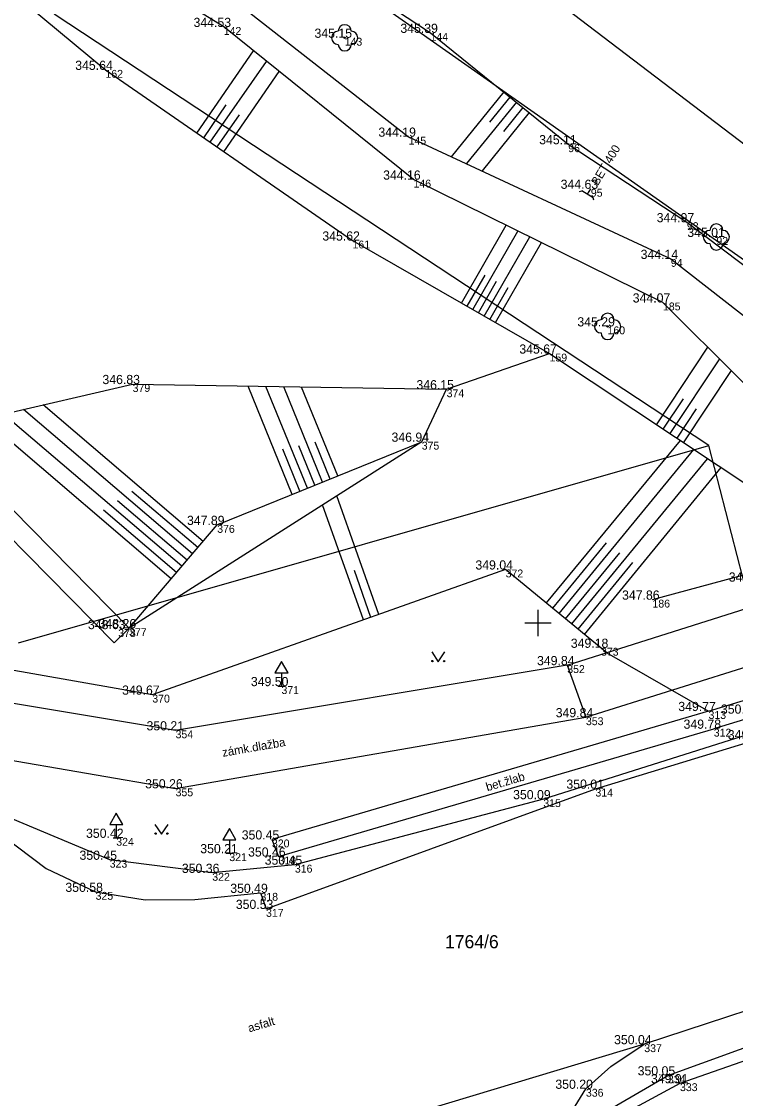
# Model space of a CAD drawing. Extents: x -614046 to -613877, y -1156755 to -1156623.
# Drawn here: x -613975.76 to -613953.98, y -1156734.51 to -1156701.64 of the extents above; entities that cross this region are included whole.
import ezdxf

# ---------------------------------------------------------------- set-up
doc = ezdxf.new("R2010")
doc.units = 0
for name, color, linetype in [('1-bod', 7, 'Continuous'), ('10-silnice', 7, 'Continuous'), ('11-zpevněné plochy', 7, 'Continuous'), ('14-terénní hrany', 7, 'Continuous'), ('15-šrafy', 7, 'Continuous'), ('16-vodní tok', 7, 'Continuous'), ('2-bod výška', 7, 'Continuous'), ('22-stromy', 7, 'Continuous'), ('27-kanalizace značky', 7, 'Continuous'), ('3-bod číslo', 7, 'Continuous'), ('34-dopravní značky', 7, 'Continuous'), ('36-Značky kultur', 7, 'Continuous'), ('40-popisy povrchů', 7, 'Continuous'), ('50-hranice parcel KN', 7, 'Continuous'), ('61-hektarová síť', 7, 'Continuous'), ('7-plot', 7, 'Continuous'), ('9-zábradlí svodidlo', 7, 'Continuous')]:
    doc.layers.add(name, color=color, linetype=linetype)

# ---------------------------------------------------------------- blocks, each defined once
blk = doc.blocks.new('3.13_1')
at = {"layer": '22-stromy'}
blk.add_circle((0, 0), 0.05, dxfattribs=at)
for centre, start, end in [((0, 0.5), 0, 180), ((-0.5, 0), 90, 270), ((0.5, 0), 270, 90), ((0, -0.5), 180, 0)]:
    blk.add_arc(centre, 0.5, start, end, dxfattribs=at)
blk = doc.blocks.new('5.270')
at = {"layer": '34-dopravní značky'}
for p, q in [((0.001, 1.02), (0.001, 0.001)), ((-0.249, 0.002), (0.251, 0.002))]:
    blk.add_line(p, q, dxfattribs=at)
blk.add_lwpolyline([(-0.499, 1.019), (0.501, 1.02), (0.001, 1.884)], close=True, dxfattribs=at)
blk = doc.blocks.new('VT')
at = {"layer": '27-kanalizace značky'}
for p, q in [((-0.629, 0.641), (-0.488, 0.5)), ((-0.488, -0.5), (-0.488, 0.5)), ((-0.488, 0), (0, 0)), ((-0.629, -0.641), (-0.488, -0.5))]:
    blk.add_line(p, q, dxfattribs=at)
blk = doc.blocks.new('3.14')
at = {"layer": '36-Značky kultur'}
blk.add_lwpolyline([(-0.5, 0.75), (0, 0), (0.5, 0.75)], dxfattribs=at)
for centre in [(-0.45, 0.05), (0.449, 0.05)]:
    blk.add_circle(centre, 0.05, dxfattribs=at)
blk = doc.blocks.new('POINT_DISPLAY')
blk.add_line((0, 0), (0, 0))

msp = doc.modelspace()

# ---------------------------------------------------------------- linework, layer by layer
at = {"layer": '10-silnice'}
for points in [[(-614040.86, -1156670.12), (-614026.04, -1156676.19), (-614020.49, -1156678.89), (-614017.81, -1156680.62), (-614014.97, -1156682.84), (-614010.02, -1156687.67), (-614005.03, -1156692.4), (-614001.46, -1156696.62), (-613996.56, -1156702.86), (-613991.22, -1156709.86), (-613982.03, -1156721.02), (-613980.56, -1156722.02), (-613978.09, -1156724.42), (-613976.34, -1156726.49), (-613975.01, -1156727.5), (-613973.5, -1156728.21), (-613971.99, -1156728.45), (-613970.47, -1156728.44), (-613968.47, -1156728.24), (-613968.3, -1156728.73), (-613958.25, -1156725.06), (-613953.29, -1156723.55)], [(-613903.37, -1156719.95), (-613913.49, -1156721.34), (-613924.71, -1156723.64), (-613933.07, -1156725.62), (-613940.71, -1156727.79), (-613951.06, -1156730.99), (-613956.76, -1156732.86), (-613974.57, -1156738.23), (-613984.2, -1156741.44), (-613994.97, -1156744.83), (-613999.58, -1156745.99)], [(-613959.8, -1156738.57), (-613959.59, -1156736.54), (-613959.25, -1156735.36), (-613958.54, -1156734.22), (-613957.78, -1156733.54), (-613956.76, -1156732.86)]]:
    msp.add_lwpolyline(points, dxfattribs=at)
at = {"layer": '11-zpevněné plochy'}
for p, q in [((-613959.11, -1156721.29), (-613935.9, -1156713.93)), ((-613956.51, -1156719.29), (-613939.14, -1156714.57)), ((-613958.54, -1156722.88), (-613935.4, -1156715.58)), ((-613954.8, -1156722.69), (-613948.43, -1156720.74)), ((-613959.11, -1156721.29), (-613971.06, -1156723.28)), ((-613959.11, -1156721.29), (-613958.54, -1156722.88)), ((-613948.23, -1156721.29), (-613954.64, -1156723.23)), ((-613971.06, -1156723.28), (-613980.5, -1156721.71)), ((-613971.06, -1156725.05), (-613958.54, -1156722.88)), ((-613954.8, -1156722.69), (-613968.12, -1156726.61)), ((-613967.92, -1156727.13), (-613954.64, -1156723.23)), ((-613978.21, -1156723.83), (-613971.06, -1156725.05)), ((-613968.12, -1156726.61), (-613967.92, -1156727.13))]:
    msp.add_line(p, q, dxfattribs=at)
at = {"layer": '14-terénní hrany'}
for p, q in [((-613965.66, -1156708.33), (-613959.65, -1156711.78)), ((-613962.79, -1156712.87), (-613959.65, -1156711.78)), ((-613959.65, -1156711.78), (-613951.27, -1156717.35)), ((-613978.43, -1156714.12), (-613972.37, -1156712.71)), ((-613972.37, -1156712.71), (-613962.79, -1156712.87)), ((-613963.55, -1156714.47), (-613962.79, -1156712.87)), ((-613963.55, -1156714.47), (-613972.48, -1156720.16)), ((-613969.79, -1156717.01), (-613963.55, -1156714.47)), ((-613972.48, -1156720.16), (-613969.79, -1156717.01)), ((-613957.9, -1156720.91), (-613954.8, -1156722.69))]:
    msp.add_line(p, q, dxfattribs=at)
for points in [[(-613997.04, -1156660.09), (-613993.56, -1156668.05), (-613988.66, -1156677.73), (-613984.98, -1156684.14), (-613979.93, -1156688.52), (-613976.6, -1156692.93), (-613968.24, -1156698.72), (-613963.28, -1156701.99), (-613959.08, -1156705.39), (-613955.46, -1156707.77), (-613951.07, -1156711.08), (-613944.86, -1156716.28)], [(-614005.92, -1156687.57), (-614003.52, -1156687.55), (-613999.15, -1156686.93), (-613994.95, -1156687.2), (-613987.2, -1156691), (-613985.24, -1156692.76), (-613978.94, -1156698.35), (-613973.2, -1156703.12), (-613965.66, -1156708.33)], [(-613957.9, -1156720.91), (-613960.99, -1156718.37), (-613971.77, -1156722.19), (-613979.82, -1156720.78), (-613982.37, -1156717.47), (-613989.67, -1156708.83), (-613995.3, -1156702.47), (-613999.07, -1156697.52), (-614001.95, -1156691.96)], [(-613958.96, -1156738.51), (-613958.16, -1156736.27), (-613957.15, -1156734.85), (-613955.67, -1156734.05), (-613950.52, -1156732.25), (-613932.98, -1156727.07), (-613924.59, -1156724.84)]]:
    msp.add_lwpolyline(points, dxfattribs=at)
at = {"layer": '15-šrafy'}
for p, q in [((-613970.41, -1156705.05), (-613968.68, -1156702.54)), ((-613970, -1156705.33), (-613968.29, -1156702.86)), ((-613969.59, -1156705.62), (-613967.9, -1156703.17)), ((-613961.05, -1156703.79), (-613962.65, -1156705.77)), ((-613970.2, -1156705.19), (-613969.52, -1156704.19)), ((-613960.66, -1156704.11), (-613962.18, -1156705.98)), ((-613960.86, -1156703.95), (-613961.48, -1156704.72)), ((-613969.79, -1156705.47), (-613969.11, -1156704.49)), ((-613960.27, -1156704.42), (-613961.71, -1156706.2)), ((-613960.47, -1156704.27), (-613961.06, -1156705)), ((-613962.338, -1156710.237), (-613960.975, -1156707.862)), ((-613961.991, -1156710.436), (-613960.616, -1156708.039)), ((-613961.645, -1156710.635), (-613960.256, -1156708.216)), ((-613961.298, -1156710.834), (-613959.897, -1156708.393)), ((-613962.165, -1156710.336), (-613961.617, -1156709.382)), ((-613961.818, -1156710.535), (-613961.265, -1156709.572)), ((-613961.471, -1156710.735), (-613960.913, -1156709.763)), ((-613956.39, -1156713.95), (-613954.82, -1156711.58)), ((-613955.97, -1156714.22), (-613954.46, -1156711.94)), ((-613955.56, -1156714.5), (-613954.1, -1156712.3)), ((-613967.5, -1156716.08), (-613968.85, -1156712.77)), ((-613967.04, -1156715.89), (-613968.31, -1156712.78)), ((-613966.58, -1156715.7), (-613967.76, -1156712.79)), ((-613966.11, -1156715.51), (-613967.22, -1156712.8)), ((-613970.22, -1156717.51), (-613975.1, -1156713.34)), ((-613956.18, -1156714.09), (-613955.56, -1156713.16)), ((-613971.19, -1156718.65), (-613976.91, -1156713.77)), ((-613970.87, -1156718.27), (-613976.31, -1156713.63)), ((-613970.54, -1156717.89), (-613975.7, -1156713.49)), ((-613955.76, -1156714.36), (-613955.17, -1156713.47)), ((-613959.74, -1156719.39), (-613955.66, -1156714.43)), ((-613967.27, -1156715.98), (-613967.79, -1156714.7)), ((-613966.81, -1156715.8), (-613967.3, -1156714.59)), ((-613966.34, -1156715.61), (-613966.8, -1156714.48)), ((-613959.36, -1156719.71), (-613955.25, -1156714.71)), ((-613958.97, -1156720.03), (-613954.83, -1156714.99)), ((-613958.58, -1156720.35), (-613954.41, -1156715.26)), ((-613970.38, -1156717.7), (-613972.39, -1156715.99)), ((-613970.71, -1156718.08), (-613972.83, -1156716.27)), ((-613965.33, -1156719.91), (-613966.58, -1156716.4)), ((-613964.86, -1156719.74), (-613966.14, -1156716.12)), ((-613971.03, -1156718.46), (-613973.26, -1156716.56)), ((-613959.55, -1156719.55), (-613957.91, -1156717.56)), ((-613959.16, -1156719.87), (-613957.51, -1156717.86)), ((-613958.78, -1156720.19), (-613957.11, -1156718.16)), ((-613965.1, -1156719.83), (-613965.6, -1156718.4))]:
    msp.add_line(p, q, dxfattribs=at)
at = {"layer": '16-vodní tok'}
for points in [[(-614001.52, -1156651.1), (-613998.11, -1156660.56), (-613996.01, -1156668.21), (-613990.4, -1156679.18), (-613986.72, -1156685.51), (-613977.75, -1156695.09), (-613969.35, -1156700.93), (-613963.95, -1156705.16), (-613955.95, -1156708.89), (-613951.7, -1156712.2), (-613945.56, -1156718.87), (-613945.478, -1156720.252)], [(-613947.4, -1156720.89), (-613951.41, -1156714.98), (-613956.19, -1156710.22), (-613963.8, -1156706.47), (-613969.59, -1156701.81), (-613978.15, -1156696.55), (-613986.41, -1156688.9), (-613987.27, -1156689.02), (-613988.53, -1156686.84), (-613992.1, -1156680.8), (-613997.89, -1156668.2), (-613999.34, -1156662.5), (-614003.52, -1156652.97)]]:
    msp.add_lwpolyline(points, dxfattribs=at)
at = {"layer": '50-hranice parcel KN'}
for points in [[(-613943.81, -1156712.94), (-613974.5, -1156689.56)], [(-613947.86, -1156713.04), (-613979.96, -1156690.49)], [(-613954.79, -1156714.58), (-613974.76, -1156701.42)], [(-613975.85, -1156720.61), (-613954.79, -1156714.58)], [(-613952.72, -1156722.64), (-613954.79, -1156714.58)]]:
    msp.add_lwpolyline(points, dxfattribs=at)
at = {"layer": '61-hektarová síť'}
for points in [[(-613960, -1156720.4), (-613960, -1156720), (-613960, -1156719.6)], [(-613960.4, -1156720), (-613960, -1156720), (-613959.6, -1156720)]]:
    msp.add_lwpolyline(points, dxfattribs=at)
at = {"layer": '7-plot'}
for points in [[(-613995.97, -1156697.53), (-613982.98, -1156709.87), (-613978.43, -1156714.12), (-613972.48, -1156720.16)], [(-613996.41, -1156697.99), (-613983.42, -1156710.33), (-613978.87, -1156714.58), (-613972.93, -1156720.61)], [(-613972.93, -1156720.61), (-613972.48, -1156720.16)]]:
    msp.add_lwpolyline(points, dxfattribs=at)
at = {"layer": '9-zábradlí svodidlo'}
for points in [[(-613926.75, -1156714.92), (-613959.84, -1156725.38), (-613967.42, -1156727.38), (-613969.94, -1156727.63), (-613973.07, -1156727.23), (-613976.34, -1156725.86), (-613978.17, -1156724.15)], [(-613959.41, -1156738.45), (-613959.23, -1156736.96), (-613958.04, -1156734.97), (-613956.04, -1156733.81), (-613950.63, -1156731.85), (-613933.17, -1156726.82), (-613924.58, -1156724.54), (-613912.88, -1156722.2), (-613903.26, -1156721.01)]]:
    msp.add_lwpolyline(points, dxfattribs=at)

# ---------------------------------------------------------------- block references
at = {"layer": '1-bod'}
for p in [(-613969.59, -1156701.81), (-613965.9, -1156702.14), (-613963.28, -1156701.99), (-613973.2, -1156703.12), (-613963.95, -1156705.16), (-613959.08, -1156705.39), (-613963.8, -1156706.47), (-613958.39, -1156706.75), (-613955.46, -1156707.77), (-613965.66, -1156708.33), (-613954.56, -1156708.22), (-613955.95, -1156708.89), (-613956.19, -1156710.22), (-613957.88, -1156710.95), (-613959.65, -1156711.78), (-613972.37, -1156712.71), (-613962.79, -1156712.87), (-613963.55, -1156714.47), (-613969.79, -1156717.01), (-613960.99, -1156718.37), (-613956.51, -1156719.29), (-613972.81, -1156720.19), (-613972.48, -1156720.16), (-613958.08, -1156720.76), (-613959.11, -1156721.29), (-613967.83, -1156721.93), (-613971.77, -1156722.19), (-613958.54, -1156722.88), (-613954.8, -1156722.69), (-613971.06, -1156723.28), (-613954.64, -1156723.23), (-613971.06, -1156725.05), (-613958.25, -1156725.06), (-613959.84, -1156725.38), (-613972.87, -1156726.56), (-613968.12, -1156726.61), (-613973.07, -1156727.23), (-613969.42, -1156727.03), (-613967.92, -1156727.13), (-613967.42, -1156727.38), (-613969.94, -1156727.63), (-613973.5, -1156728.21), (-613968.47, -1156728.24), (-613968.3, -1156728.73), (-613956.76, -1156732.86), (-613956.04, -1156733.81), (-613955.67, -1156734.05), (-613958.54, -1156734.22)]:
    msp.add_blockref('POINT_DISPLAY', p, dxfattribs=at)
at = {"layer": '22-stromy', "xscale": 0.4, "yscale": 0.4000000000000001}
for p in [(-613965.9, -1156702.14), (-613954.56, -1156708.22), (-613957.88, -1156710.95)]:
    msp.add_blockref('3.13_1', p, dxfattribs=at)
at = {"layer": '27-kanalizace značky', "xscale": 0.39999999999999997, "yscale": 0.4, "rotation": 58.61536191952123}
msp.add_blockref('VT', (-613958.39, -1156706.75), dxfattribs=at)
at = {"layer": '34-dopravní značky', "xscale": 0.4, "yscale": 0.4000000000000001}
for p in [(-613967.83, -1156721.93), (-613972.87, -1156726.56), (-613969.42, -1156727.03)]:
    msp.add_blockref('5.270', p, dxfattribs=at)
at = {"layer": '36-Značky kultur', "xscale": 0.4, "yscale": 0.4000000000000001}
for p in [(-613963.045, -1156721.186), (-613971.489, -1156726.452)]:
    msp.add_blockref('3.14', p, dxfattribs=at)

# ---------------------------------------------------------------- texts
at = {"layer": '2-bod výška'}
for s, p in [('344.53 ', (-613970.512, -1156701.81)), ('345.15 ', (-613966.822, -1156702.14)), ('345.39 ', (-613964.202, -1156701.99)), ('345.64 ', (-613974.122, -1156703.12)), ('344.19 ', (-613964.872, -1156705.16)), ('345.11 ', (-613959.967, -1156705.39)), ('344.16 ', (-613964.728, -1156706.47)), ('344.63 ', (-613959.312, -1156706.75)), ('344.97 ', (-613956.382, -1156707.77)), ('345.62 ', (-613966.582, -1156708.33)), ('345.01 ', (-613955.447, -1156708.22)), ('344.14 ', (-613956.872, -1156708.89)), ('344.07 ', (-613957.112, -1156710.22)), ('345.29 ', (-613958.802, -1156710.95)), ('345.67 ', (-613960.572, -1156711.78)), ('346.83 ', (-613973.292, -1156712.71)), ('346.15 ', (-613963.712, -1156712.87)), ('346.94 ', (-613964.472, -1156714.47)), ('347.89 ', (-613970.712, -1156717.01)), ('349.04 ', (-613961.912, -1156718.37)), ('346.87 ', (-613954.182, -1156718.74)), ('347.86 ', (-613957.438, -1156719.29)), ('348.63 ', (-613973.732, -1156720.19)), ('348.26 ', (-613973.408, -1156720.16)), ('349.18 ', (-613959.002, -1156720.76)), ('349.84 ', (-613960.032, -1156721.29)), ('349.50 ', (-613968.763, -1156721.93)), ('349.67 ', (-613972.692, -1156722.19)), ('349.84 ', (-613959.462, -1156722.88)), ('349.77 ', (-613955.722, -1156722.69)), ('350.03 ', (-613954.422, -1156722.77)), ('349.78 ', (-613955.562, -1156723.23)), ('350.21 ', (-613971.947, -1156723.28)), ('349.84 ', (-613954.212, -1156723.55)), ('350.26 ', (-613971.988, -1156725.05)), ('350.01 ', (-613959.137, -1156725.06)), ('350.09 ', (-613960.762, -1156725.38)), ('350.42 ', (-613973.792, -1156726.56)), ('350.45 ', (-613969.042, -1156726.61)), ('350.21 ', (-613970.307, -1156727.03)), ('350.46 ', (-613968.848, -1156727.13)), ('350.45 ', (-613973.992, -1156727.23)), ('350.45 ', (-613968.342, -1156727.38)), ('350.36 ', (-613970.868, -1156727.63)), ('350.58 ', (-613974.422, -1156728.21)), ('350.49 ', (-613969.392, -1156728.24)), ('350.53 ', (-613969.222, -1156728.73)), ('350.04 ', (-613957.682, -1156732.86)), ('350.05 ', (-613956.962, -1156733.81)), ('349.91 ', (-613956.557, -1156734.05)), ('350.20 ', (-613959.473, -1156734.22))]:
    msp.add_text(s, height=0.28, dxfattribs=at).set_placement(p)
at = {"layer": '3-bod číslo'}
for s, p in [('142', (-613969.59, -1156702.05)), ('143', (-613965.9, -1156702.38)), ('144', (-613963.28, -1156702.23)), ('162', (-613973.2, -1156703.36)), ('145', (-613963.95, -1156705.4)), ('96', (-613959.08, -1156705.63)), ('146', (-613963.8, -1156706.71)), ('95', (-613958.39, -1156706.99)), ('93', (-613955.46, -1156708.01)), ('161', (-613965.66, -1156708.57)), ('92', (-613954.56, -1156708.46)), ('94', (-613955.95, -1156709.13)), ('185', (-613956.19, -1156710.46)), ('160', (-613957.88, -1156711.19)), ('159', (-613959.65, -1156712.02)), ('379', (-613972.37, -1156712.95)), ('374', (-613962.79, -1156713.11)), ('375', (-613963.55, -1156714.71)), ('376', (-613969.79, -1156717.25)), ('372', (-613960.99, -1156718.61)), ('186', (-613956.51, -1156719.53)), ('378', (-613972.81, -1156720.43)), ('377', (-613972.48, -1156720.4)), ('373', (-613958.08, -1156721)), ('352', (-613959.11, -1156721.53)), ('371', (-613967.83, -1156722.17)), ('370', (-613971.77, -1156722.43)), ('353', (-613958.54, -1156723.12)), ('313', (-613954.8, -1156722.93)), ('354', (-613971.06, -1156723.52)), ('312', (-613954.64, -1156723.47)), ('355', (-613971.06, -1156725.29)), ('314', (-613958.25, -1156725.3)), ('315', (-613959.84, -1156725.62)), ('324', (-613972.87, -1156726.8)), ('320', (-613968.12, -1156726.85)), ('323', (-613973.07, -1156727.47)), ('321', (-613969.42, -1156727.27)), ('319', (-613967.92, -1156727.37)), ('316', (-613967.42, -1156727.62)), ('322', (-613969.94, -1156727.87)), ('325', (-613973.5, -1156728.45)), ('318', (-613968.47, -1156728.48)), ('317', (-613968.3, -1156728.97)), ('337', (-613956.76, -1156733.1)), ('334', (-613956.04, -1156734.05)), ('333', (-613955.67, -1156734.29)), ('336', (-613958.54, -1156734.46))]:
    msp.add_text(s, height=0.24, dxfattribs=at).set_placement(p)
at = {"layer": '40-popisy povrchů'}
for s, rotation, p in [('BET 400', 58.9631, (-613958.175, -1156706.667)), ('zámk.dlažba', 9.833, (-613969.617, -1156724.088)), ('bet.žlab', 16.3662, (-613961.55, -1156725.14)), ('asfalt', 16.7789, (-613968.81, -1156732.5))]:
    msp.add_text(s, height=0.26, rotation=rotation, dxfattribs=at).set_placement(p)
at = {"layer": '50-hranice parcel KN'}
msp.add_text('1764/6', height=0.4, dxfattribs=at).set_placement((-613962.839, -1156729.93))

doc.saveas('drawing.dxf')
